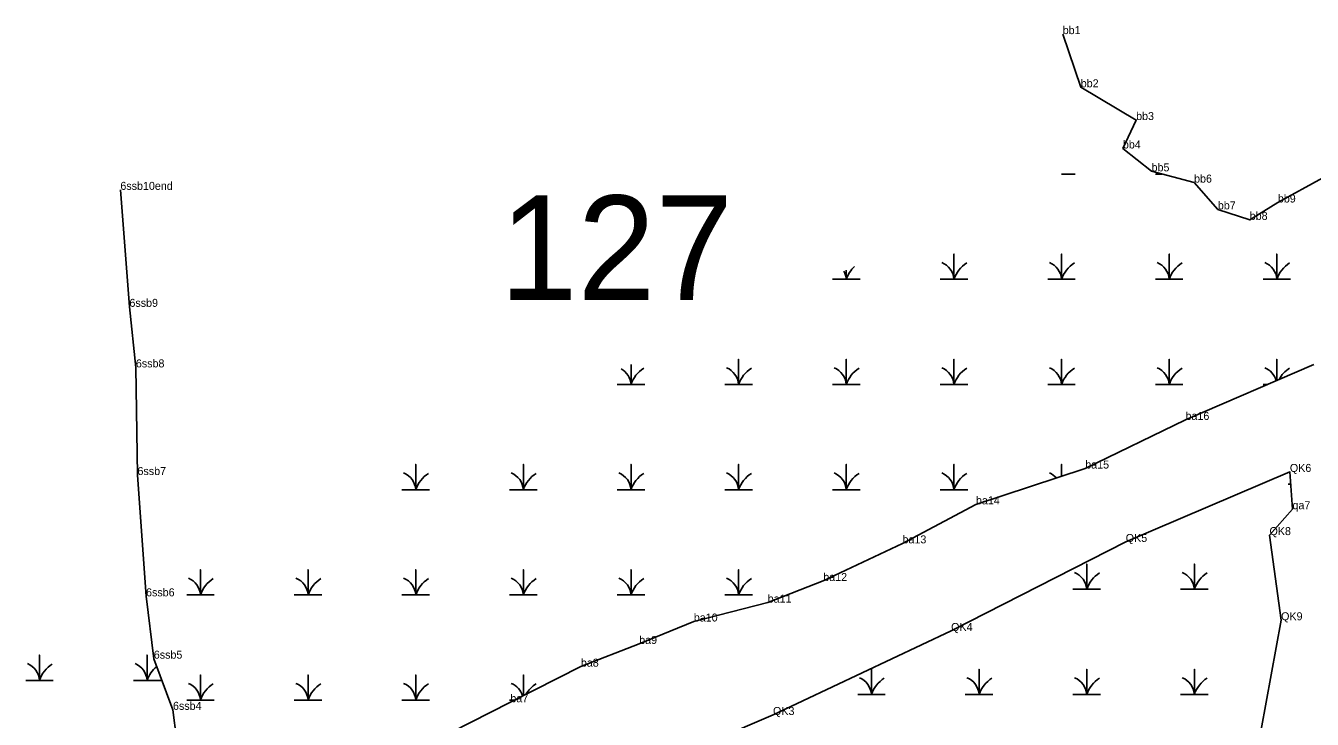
# Model space of a CAD drawing. Extents: x 2072529 to 2268796, y 436423 to 470397.
# Drawn here: x 2153359 to 2154163, y 438734 to 439167 of the extents above; entities that cross this region are included whole.
import ezdxf

# ---------------------------------------------------------------- set-up
doc = ezdxf.new("R2010")
doc.units = 0
for name, color, linetype in [('Default', 7, 'Continuous'), ('Exist Environmental Wetland Boundary', 7, 'Continuous'), ('Exist Environmental Wetland Boundary Cogo Comment', 7, 'Continuous'), ('Exist Environmental Wetland Boundary Cogo Point CELL', 7, 'Continuous'), ('Exist Hydro Jurisdictional Stream or Body of Water NEU Mitigable', 7, 'Continuous'), ('Exist Hydro Jurisdictional Stream or Body of Water NEU Mitigable Cogo Comment', 7, 'Continuous'), ('Exist Hydro Swamp or Marsh', 7, 'Continuous')]:
    doc.layers.add(name, color=color, linetype=linetype)

msp = doc.modelspace()

# ---------------------------------------------------------------- linework, layer by layer
at = {"layer": 'Exist Environmental Wetland Boundary'}
for points in [[(2154007.21, 439162.22), (2154018.48, 439128.98), (2154053.07, 439108.49), (2154044.8, 439090.71), (2154062.72, 439076.41), (2154089.29, 439069.36), (2154104.13, 439052.62), (2154124.06, 439046.04), (2154141.63, 439056.91), (2154169.65, 439072.41)], [(2153527.37, 438629.46), (2153503.31, 438654.33), (2153506.4, 438671.17), (2153529.85, 438680.72), (2153534.13, 438691.75), (2153578.44, 438707.49), (2153612.52, 438719.25), (2153662.11, 438744.35), (2153706.16, 438766.61), (2153742.6, 438780.8), (2153776.72, 438794.85), (2153822.89, 438806.64), (2153857.62, 438820.19), (2153907.12, 438843.71), (2153953.02, 438868.13), (2154021.3, 438890.53), (2154083.94, 438920.93), (2154164.03, 438955.62)], [(2153527.37, 438629.46), (2153606.57, 438642.14), (2153826.22, 438736.39), (2153937.5, 438788.93), (2154046.6, 438844.6), (2154149.14, 438888.4), (2154150.77, 438865.09), (2154136.41, 438848.89), (2154143.66, 438795.63), (2154131.16, 438727.3), (2154133.8, 438691.78)]]:
    msp.add_lwpolyline(points, dxfattribs=at)
at = {"layer": 'Exist Environmental Wetland Boundary Cogo Point CELL'}
for p, q in [((2154007.21, 439162.22), (2154007.21, 439162.22)), ((2154018.48, 439128.98), (2154018.48, 439128.98)), ((2154053.07, 439108.49), (2154053.07, 439108.49)), ((2154044.8, 439090.71), (2154044.8, 439090.71)), ((2154062.72, 439076.41), (2154062.72, 439076.41)), ((2153418.44, 439064.82), (2153418.44, 439064.82)), ((2154089.29, 439069.36), (2154089.29, 439069.36)), ((2154141.63, 439056.91), (2154141.63, 439056.91)), ((2154104.13, 439052.62), (2154104.13, 439052.62)), ((2154124.06, 439046.04), (2154124.06, 439046.04)), ((2153424.11, 438991.65), (2153424.11, 438991.65)), ((2153428.13, 438953.78), (2153428.13, 438953.78)), ((2154083.94, 438920.93), (2154083.94, 438920.93)), ((2153429.14, 438886.46), (2153429.14, 438886.46)), ((2154021.3, 438890.53), (2154021.3, 438890.53)), ((2154149.14, 438888.4), (2154149.14, 438888.4)), ((2153953.02, 438868.13), (2153953.02, 438868.13)), ((2154150.77, 438865.09), (2154150.77, 438865.09)), ((2154046.6, 438844.6), (2154046.6, 438844.6)), ((2154136.41, 438848.89), (2154136.41, 438848.89)), ((2153907.12, 438843.71), (2153907.12, 438843.71)), ((2153857.62, 438820.19), (2153857.62, 438820.19)), ((2153434.48, 438810.6), (2153434.48, 438810.6)), ((2153822.89, 438806.64), (2153822.89, 438806.64)), ((2153776.72, 438794.85), (2153776.72, 438794.85)), ((2153937.5, 438788.93), (2153937.5, 438788.93)), ((2154143.66, 438795.63), (2154143.66, 438795.63)), ((2153742.6, 438780.8), (2153742.6, 438780.8)), ((2153439.32, 438771.61), (2153439.32, 438771.61)), ((2153706.16, 438766.61), (2153706.16, 438766.61)), ((2153662.11, 438744.35), (2153662.11, 438744.35)), ((2153451.31, 438739.61), (2153451.31, 438739.61)), ((2153826.22, 438736.39), (2153826.22, 438736.39))]:
    msp.add_line(p, q, dxfattribs=at)
at = {"layer": 'Exist Hydro Jurisdictional Stream or Body of Water NEU Mitigable'}
msp.add_lwpolyline([(2153424.24, 438582.83), (2153436.6, 438624.69), (2153449.69, 438661.35), (2153455.83, 438703.7), (2153451.31, 438739.61), (2153439.32, 438771.61), (2153434.48, 438810.6), (2153429.14, 438886.46), (2153428.13, 438953.78), (2153424.11, 438991.65), (2153418.44, 439064.82)], dxfattribs=at)
at = {"layer": 'Exist Hydro Swamp or Marsh'}
for points in [[(2154006.5, 439074.68), (2154015.08, 439074.68)], [(2154065.13, 439074.68), (2154069.23, 439074.68)], [(2153930.63, 439008.88), (2153939.23, 439008.88), (2153939.23, 439024.66), (2153939.23, 439008.88), (2153947.83, 439008.88)], [(2153997.88, 439008.88), (2154006.48, 439008.88), (2154006.48, 439024.66), (2154006.48, 439008.88), (2154015.08, 439008.88)], [(2154065.13, 439008.88), (2154073.73, 439008.88), (2154073.73, 439024.66), (2154073.73, 439008.88), (2154082.33, 439008.88)], [(2154132.38, 439008.88), (2154140.98, 439008.88), (2154140.98, 439024.66), (2154140.98, 439008.88), (2154149.58, 439008.88)], [(2153863.38, 439008.88), (2153871.98, 439008.88), (2153871.98, 439014.61)], [(2153871.98, 439014.61), (2153871.98, 439008.88), (2153880.58, 439008.88)], [(2153796.13, 438943.08), (2153804.73, 438943.08), (2153804.73, 438958.86), (2153804.73, 438943.08), (2153813.33, 438943.08)], [(2153863.38, 438943.08), (2153871.98, 438943.08), (2153871.98, 438958.86), (2153871.98, 438943.08), (2153880.58, 438943.08)], [(2153930.63, 438943.08), (2153939.23, 438943.08), (2153939.23, 438958.86), (2153939.23, 438943.08), (2153947.83, 438943.08)], [(2153997.88, 438943.08), (2154006.48, 438943.08), (2154006.48, 438958.86), (2154006.48, 438943.08), (2154015.08, 438943.08)], [(2154065.13, 438943.08), (2154073.73, 438943.08), (2154073.73, 438958.86), (2154073.73, 438943.08), (2154082.33, 438943.08)], [(2154140.98, 438945.64), (2154140.98, 438958.86), (2154140.98, 438945.64)], [(2153728.88, 438943.08), (2153737.48, 438943.08), (2153737.48, 438955.64)], [(2153737.48, 438955.64), (2153737.48, 438943.08), (2153746.08, 438943.08)], [(2154132.38, 438943.08), (2154135.09, 438943.08)], [(2153594.38, 438877.28), (2153602.98, 438877.28), (2153602.98, 438893.06), (2153602.98, 438877.28), (2153611.58, 438877.28)], [(2153661.63, 438877.28), (2153670.23, 438877.28), (2153670.23, 438893.06), (2153670.23, 438877.28), (2153678.83, 438877.28)], [(2153728.88, 438877.28), (2153737.48, 438877.28), (2153737.48, 438893.06), (2153737.48, 438877.28), (2153746.08, 438877.28)], [(2153796.13, 438877.28), (2153804.73, 438877.28), (2153804.73, 438893.06), (2153804.73, 438877.28), (2153813.33, 438877.28)], [(2153863.38, 438877.28), (2153871.98, 438877.28), (2153871.98, 438893.06), (2153871.98, 438877.28), (2153880.58, 438877.28)], [(2153930.63, 438877.28), (2153939.23, 438877.28), (2153939.23, 438893.06), (2153939.23, 438877.28), (2153947.83, 438877.28)], [(2154006.48, 438885.67), (2154006.48, 438893.06), (2154006.48, 438885.67)], [(2154148.11, 438880.81), (2154149.67, 438880.81)], [(2154013.61, 438815.01), (2154022.21, 438815.01), (2154022.21, 438830.79), (2154022.21, 438815.01), (2154030.81, 438815.01)], [(2154080.86, 438815.01), (2154089.46, 438815.01), (2154089.46, 438830.79), (2154089.46, 438815.01), (2154098.06, 438815.01)], [(2153459.88, 438811.48), (2153468.48, 438811.48), (2153468.48, 438827.26), (2153468.48, 438811.48), (2153477.08, 438811.48)], [(2153527.13, 438811.48), (2153535.73, 438811.48), (2153535.73, 438827.26), (2153535.73, 438811.48), (2153544.33, 438811.48)], [(2153594.38, 438811.48), (2153602.98, 438811.48), (2153602.98, 438827.26), (2153602.98, 438811.48), (2153611.58, 438811.48)], [(2153661.63, 438811.48), (2153670.23, 438811.48), (2153670.23, 438827.26), (2153670.23, 438811.48), (2153678.83, 438811.48)], [(2153728.88, 438811.48), (2153737.48, 438811.48), (2153737.48, 438827.26), (2153737.48, 438811.48), (2153746.08, 438811.48)], [(2153796.13, 438811.48), (2153804.73, 438811.48), (2153804.73, 438827.26), (2153804.73, 438811.48), (2153813.33, 438811.48)], [(2153871.98, 438827.01), (2153871.98, 438827.26), (2153871.98, 438827.01)], [(2153359.31, 438758.03), (2153367.91, 438758.03), (2153367.91, 438773.81), (2153367.91, 438758.03), (2153376.51, 438758.03)], [(2153426.56, 438758.03), (2153435.16, 438758.03), (2153435.16, 438773.81), (2153435.16, 438758.03), (2153443.76, 438758.03)], [(2153879.11, 438749.21), (2153887.71, 438749.21), (2153887.71, 438764.99), (2153887.71, 438749.21), (2153896.31, 438749.21)], [(2153946.36, 438749.21), (2153954.96, 438749.21), (2153954.96, 438764.99), (2153954.96, 438749.21), (2153963.56, 438749.21)], [(2154013.61, 438749.21), (2154022.21, 438749.21), (2154022.21, 438764.99), (2154022.21, 438749.21), (2154030.81, 438749.21)], [(2154080.86, 438749.21), (2154089.46, 438749.21), (2154089.46, 438764.99), (2154089.46, 438749.21), (2154098.06, 438749.21)], [(2153459.88, 438745.68), (2153468.48, 438745.68), (2153468.48, 438761.46), (2153468.48, 438745.68), (2153477.08, 438745.68)], [(2153527.13, 438745.68), (2153535.73, 438745.68), (2153535.73, 438761.46), (2153535.73, 438745.68), (2153544.33, 438745.68)], [(2153594.38, 438745.68), (2153602.98, 438745.68), (2153602.98, 438761.46), (2153602.98, 438745.68), (2153611.58, 438745.68)], [(2153670.23, 438748.46), (2153670.23, 438761.46), (2153670.23, 438748.46)], [(2153661.63, 438745.68), (2153664.74, 438745.68)]]:
    msp.add_lwpolyline(points, dxfattribs=at)
for centre, radius, start, end in [((2153859.72, 439008), 12.3, 4.14034, 28.89149), ((2153890.22, 439002.82), 19.22, 132.85147, 161.62219), ((2153926.97, 439008), 12.3, 4.14034, 67.53497), ((2153957.47, 439002.82), 19.22, 122.12745, 161.62219), ((2153994.22, 439008), 12.3, 4.14034, 67.53497), ((2154024.72, 439002.82), 19.22, 122.12745, 161.62219), ((2154061.47, 439008), 12.3, 4.14034, 67.53497), ((2154091.97, 439002.82), 19.22, 122.12745, 161.62219), ((2154128.72, 439008), 12.3, 4.14034, 67.53497), ((2154159.22, 439002.82), 19.22, 122.12745, 161.62219), ((2153725.22, 438942.2), 12.3, 4.14034, 60.69278), ((2153755.72, 438937.02), 19.22, 122.12745, 161.62219), ((2153792.47, 438942.2), 12.3, 4.14034, 67.53497), ((2153822.97, 438937.02), 19.22, 122.12745, 161.62219), ((2153859.72, 438942.2), 12.3, 4.14034, 67.53497), ((2153890.22, 438937.02), 19.22, 122.12745, 161.62219), ((2153926.97, 438942.2), 12.3, 4.14034, 67.53497), ((2153957.47, 438937.02), 19.22, 122.12745, 161.62219), ((2153994.22, 438942.2), 12.3, 4.14034, 67.53497), ((2154024.72, 438937.02), 19.22, 122.12745, 161.62219), ((2154061.47, 438942.2), 12.3, 4.14034, 67.53497), ((2154091.97, 438937.02), 19.22, 122.12745, 161.62219), ((2154128.72, 438942.2), 12.3, 15.39509, 67.53497), ((2154159.22, 438937.02), 19.22, 122.12745, 151.38089), ((2153590.72, 438876.4), 12.3, 4.14034, 67.53497), ((2153621.22, 438871.22), 19.22, 122.12745, 161.62219), ((2153657.97, 438876.4), 12.3, 4.14034, 67.53497), ((2153688.47, 438871.22), 19.22, 122.12745, 161.62219), ((2153725.22, 438876.4), 12.3, 4.14034, 67.53497), ((2153755.72, 438871.22), 19.22, 122.12745, 161.62219), ((2153792.47, 438876.4), 12.3, 4.14034, 67.53497), ((2153822.97, 438871.22), 19.22, 122.12745, 161.62219), ((2153859.72, 438876.4), 12.3, 4.14034, 67.53497), ((2153890.22, 438871.22), 19.22, 122.12745, 161.62219), ((2153926.97, 438876.4), 12.3, 4.14034, 67.53497), ((2153957.47, 438871.22), 19.22, 122.12745, 161.62219), ((2153994.22, 438876.4), 12.3, 42.09026, 67.53497), ((2153456.22, 438810.6), 12.3, 4.14034, 67.53497), ((2153486.72, 438805.42), 19.22, 122.12745, 161.62219), ((2153523.47, 438810.6), 12.3, 4.14034, 67.53497), ((2153553.97, 438805.42), 19.22, 122.12745, 161.62219), ((2153590.72, 438810.6), 12.3, 4.14034, 67.53497), ((2153621.22, 438805.42), 19.22, 122.12745, 161.62219), ((2153657.97, 438810.6), 12.3, 4.14034, 67.53497), ((2153688.47, 438805.42), 19.22, 122.12745, 161.62219), ((2153725.22, 438810.6), 12.3, 4.14034, 67.53497), ((2153755.72, 438805.42), 19.22, 122.12745, 161.62219), ((2153792.47, 438810.6), 12.3, 4.14034, 67.53497), ((2153822.97, 438805.42), 19.22, 122.12745, 161.62219), ((2154009.94, 438814.12), 12.3, 4.14034, 67.53497), ((2154040.45, 438808.95), 19.22, 122.12745, 161.62219), ((2154077.19, 438814.12), 12.3, 4.14034, 67.53497), ((2154107.7, 438808.95), 19.22, 122.12745, 161.62219), ((2153355.65, 438757.14), 12.3, 4.14034, 67.53497), ((2153386.15, 438751.96), 19.22, 122.12745, 161.62219), ((2153422.9, 438757.14), 12.3, 4.14034, 67.53497), ((2153453.4, 438751.96), 19.22, 129.65708, 161.62219), ((2153456.22, 438744.8), 12.3, 4.14034, 67.53497), ((2153523.47, 438744.8), 12.3, 4.14034, 67.53497), ((2153590.72, 438744.8), 12.3, 4.14034, 67.53497), ((2153657.97, 438744.8), 12.3, 16.20624, 67.53497), ((2153875.44, 438748.32), 12.3, 4.14034, 67.53497), ((2153905.95, 438743.15), 19.22, 122.12745, 161.62219), ((2153942.69, 438748.32), 12.3, 4.14034, 67.53497), ((2153973.2, 438743.15), 19.22, 122.12745, 161.62219), ((2154009.94, 438748.32), 12.3, 4.14034, 67.53497), ((2154040.45, 438743.15), 19.22, 122.12745, 161.62219), ((2154077.19, 438748.32), 12.3, 4.14034, 67.53497), ((2154107.7, 438743.15), 19.22, 122.12745, 161.62219), ((2153486.72, 438739.62), 19.22, 122.12745, 161.62219), ((2153553.97, 438739.62), 19.22, 122.12745, 161.62219), ((2153621.22, 438739.62), 19.22, 122.12745, 161.62219), ((2153688.47, 438739.62), 19.22, 122.12745, 149.8526)]:
    msp.add_arc(centre, radius, start, end, dxfattribs=at)

# ---------------------------------------------------------------- texts
at = {"layer": 'Default'}
msp.add_text('127', height=65.34, dxfattribs=at).set_placement((2153655.5, 438995.97))
at = {"layer": 'Exist Environmental Wetland Boundary Cogo Comment'}
for s, p in [('bb1', (2154007.21, 439162.22)), ('bb2', (2154018.48, 439128.98)), ('bb3', (2154053.07, 439108.49)), ('bb4', (2154044.8, 439090.71)), ('bb5', (2154062.72, 439076.41)), ('bb6', (2154089.29, 439069.36)), ('bb9', (2154141.63, 439056.91)), ('bb7', (2154104.13, 439052.62)), ('bb8', (2154124.06, 439046.04)), ('ba16', (2154083.94, 438920.93)), ('ba15', (2154021.3, 438890.53)), ('QK6', (2154149.14, 438888.4)), ('ba14', (2153953.02, 438868.13)), ('qa7', (2154150.77, 438865.09)), ('QK8', (2154136.41, 438848.89)), ('ba13', (2153907.12, 438843.71)), ('QK5', (2154046.6, 438844.6)), ('ba12', (2153857.62, 438820.19)), ('ba11', (2153822.89, 438806.64)), ('ba10', (2153776.72, 438794.85)), ('QK9', (2154143.66, 438795.63)), ('QK4', (2153937.5, 438788.93)), ('ba9', (2153742.6, 438780.8)), ('ba8', (2153706.16, 438766.61)), ('ba7', (2153662.11, 438744.35)), ('QK3', (2153826.22, 438736.39))]:
    msp.add_text(s, height=5, dxfattribs=at).set_placement(p)
at = {"layer": 'Exist Hydro Jurisdictional Stream or Body of Water NEU Mitigable Cogo Comment'}
for s, p in [('6ssb10end', (2153418.44, 439064.82)), ('6ssb9', (2153424.11, 438991.65)), ('6ssb8', (2153428.13, 438953.78)), ('6ssb7', (2153429.14, 438886.46)), ('6ssb6', (2153434.48, 438810.6)), ('6ssb5', (2153439.32, 438771.61)), ('6ssb4', (2153451.31, 438739.61))]:
    msp.add_text(s, height=5, dxfattribs=at).set_placement(p)

doc.saveas('drawing.dxf')
